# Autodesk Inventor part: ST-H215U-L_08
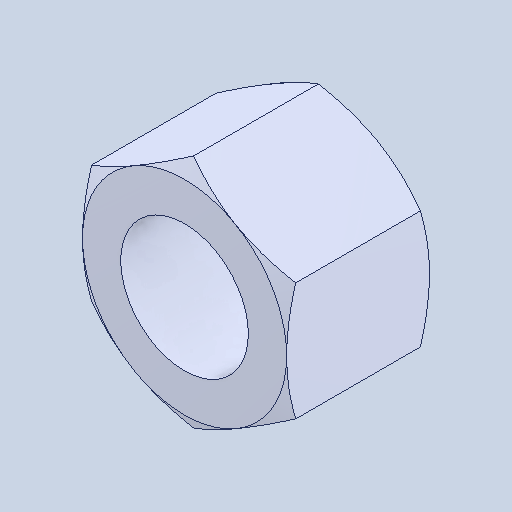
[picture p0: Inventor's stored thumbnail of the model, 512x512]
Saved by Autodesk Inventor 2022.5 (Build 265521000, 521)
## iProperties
Created: 2024-07
Part Number: ST-H215U-L_08
Material: 一般
Document SubType Name: Modeling
Designer: ImaoCorp
Density: 1 g/cm^3
Appearance: 既定
Author: ImaoCorp
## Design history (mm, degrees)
feature "ST-H215U-L_08"
node "ソリッド1"
